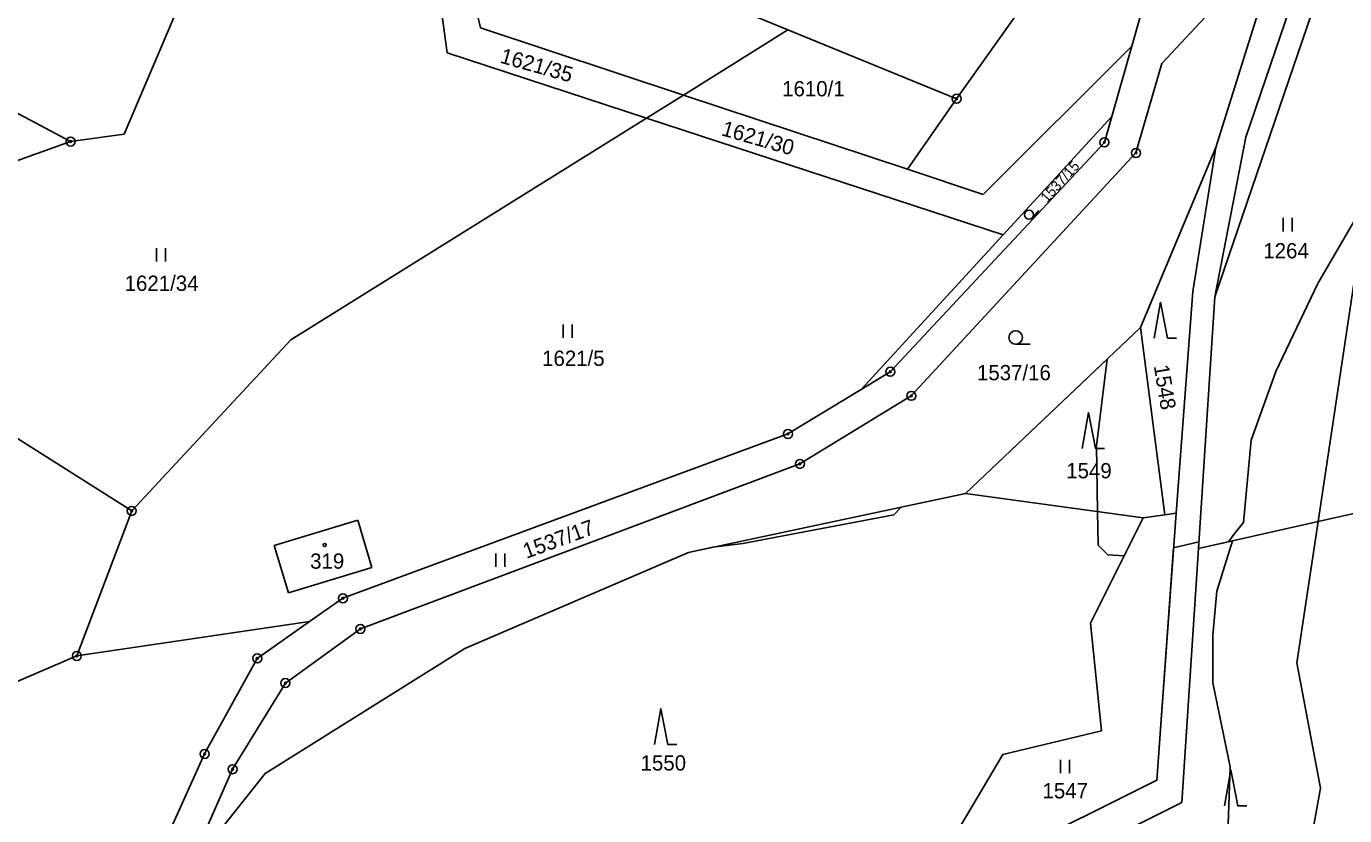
# Model space of a CAD drawing. Extents: x -445050 to -440454, y -1134563 to -1129741.
# Drawn here: x -442215.5 to -442068.8, y -1132304 to -1132216.1 of the extents above; entities that cross this region are included whole.
import ezdxf

# ---------------------------------------------------------------- set-up
doc = ezdxf.new("R2010")
doc.units = 0
for name, color, linetype in [('Vrstva 1', 7, 'Continuous'), ('Vrstva 18', 7, 'Continuous'), ('Vrstva 19', 7, 'Continuous'), ('Vrstva 24', 7, 'Continuous'), ('Vrstva 25', 7, 'Continuous'), ('Vrstva 3', 7, 'Continuous'), ('Vrstva 37', 7, 'Continuous'), ('Vrstva 52', 7, 'Continuous'), ('Vrstva 6', 7, 'Continuous')]:
    doc.layers.add(name, color=color, linetype=linetype)

msp = doc.modelspace()

# ---------------------------------------------------------------- linework, layer by layer
at = {"layer": 'Vrstva 1'}
for points in [[(-442079.79, -1132228.47), (-442069.94, -1132199.62)], [(-442168.65, -1132219.08), (-442171.25, -1132199.95)], [(-442168.53, -1132201.06), (-442130.72, -1132216.53)], [(-442168.53, -1132201.06), (-442164.95, -1132216.31)], [(-442087.74, -1132201.71), (-442092.48, -1132218.35)], [(-442250.43, -1132207.69), (-442210.55, -1132228.95)], [(-442080.57, -1132211.05), (-442089.13, -1132220.27)], [(-442083.13, -1132229.6), (-442077.5, -1132211.7)], [(-442198.19, -1132213.11), (-442204.59, -1132228.14)], [(-442104.18, -1132213.24), (-442111.96, -1132224.19)], [(-442083.23, -1132246.23), (-442072.42, -1132214.61)], [(-442164.95, -1132216.31), (-442142.36, -1132223.79)], [(-442142.36, -1132223.79), (-442130.72, -1132216.53)], [(-442130.72, -1132216.53), (-442111.96, -1132224.19)], [(-442108.99, -1132234.83), (-442092.48, -1132218.35)], [(-442092.48, -1132218.35), (-442094.7, -1132226.16)], [(-442168.65, -1132219.08), (-442146.45, -1132226.34)], [(-442089.13, -1132220.27), (-442092, -1132230.22)], [(-442146.45, -1132226.34), (-442142.36, -1132223.79)], [(-442142.36, -1132223.79), (-442117.44, -1132232.03)], [(-442111.96, -1132224.19), (-442117.44, -1132232.03)], [(-442186.05, -1132251.03), (-442146.45, -1132226.34)], [(-442146.45, -1132226.34), (-442106.78, -1132239.32)], [(-442094.7, -1132226.16), (-442106.78, -1132239.32)], [(-442094.7, -1132226.16), (-442095.52, -1132229.04)], [(-442210.55, -1132228.95), (-442232.96, -1132237.01)], [(-442204.59, -1132228.14), (-442210.55, -1132228.95)], [(-442083.23, -1132246.23), (-442079.79, -1132228.47)], [(-442119.34, -1132254.57), (-442095.52, -1132229.04)], [(-442092, -1132230.22), (-442117, -1132257.25)], [(-442091.48, -1132249.65), (-442083.13, -1132229.6)], [(-442085.69, -1132245.63), (-442083.13, -1132229.6)], [(-442071.73, -1132271.25), (-442065.52, -1132229.94)], [(-442117.44, -1132232.03), (-442108.99, -1132234.83)], [(-442106.78, -1132239.32), (-442122.59, -1132256.55)], [(-442087.54, -1132270.3), (-442085.69, -1132245.63)], [(-442083.23, -1132246.23), (-442085.05, -1132274.25)], [(-442186.05, -1132251.03), (-442203.74, -1132270.05)], [(-442091.48, -1132249.65), (-442110.98, -1132268.11)], [(-442091.48, -1132249.65), (-442088.78, -1132270.48)], [(-442119.34, -1132254.57), (-442122.59, -1132256.55)], [(-442122.59, -1132256.55), (-442130.72, -1132261.49)], [(-442117, -1132257.25), (-442129.4, -1132264.82)], [(-442217.56, -1132261.28), (-442203.74, -1132270.05)], [(-442180.25, -1132279.78), (-442130.72, -1132261.49)], [(-442129.4, -1132264.82), (-442178.3, -1132283.19)], [(-442110.98, -1132268.11), (-442141.8, -1132274.69)], [(-442110.98, -1132268.11), (-442091.21, -1132270.83)], [(-442203.74, -1132270.05), (-442209.85, -1132286.2)], [(-442178.6, -1132271.1), (-442187.88, -1132273.89)], [(-442177.02, -1132276.36), (-442178.6, -1132271.1)], [(-442091.21, -1132270.83), (-442097.06, -1132282.55)], [(-442091.21, -1132270.83), (-442088.78, -1132270.48)], [(-442089.68, -1132300.03), (-442087.54, -1132270.3)], [(-442088.78, -1132270.48), (-442087.54, -1132270.3)], [(-442085.05, -1132274.25), (-442071.73, -1132271.25)], [(-442074.09, -1132286.98), (-442071.73, -1132271.25)], [(-442187.88, -1132273.89), (-442186.3, -1132279.16)], [(-442085.05, -1132274.25), (-442086.89, -1132302.49)], [(-442141.8, -1132274.69), (-442166.69, -1132285.36)], [(-442186.3, -1132279.16), (-442177.02, -1132276.36)], [(-442183.96, -1132282.38), (-442180.25, -1132279.78)], [(-442209.85, -1132286.2), (-442183.96, -1132282.38)], [(-442189.78, -1132286.47), (-442183.96, -1132282.38)], [(-442178.3, -1132283.19), (-442186.65, -1132289.22)], [(-442097.06, -1132282.55), (-442095.83, -1132294.53)], [(-442209.85, -1132286.2), (-442254.86, -1132305.55)], [(-442166.69, -1132285.36), (-442188.9, -1132299.28)], [(-442195.63, -1132297.1), (-442189.78, -1132286.47)], [(-442071.47, -1132300.93), (-442074.09, -1132286.98)], [(-442186.65, -1132289.22), (-442192.52, -1132298.8)], [(-442095.83, -1132294.53), (-442106.83, -1132297.15)], [(-442211.4, -1132332.11), (-442195.63, -1132297.1)], [(-442106.83, -1132297.15), (-442115.37, -1132311.62)], [(-442197.5, -1132310.13), (-442192.52, -1132298.8)], [(-442188.9, -1132299.28), (-442197.5, -1132310.13)], [(-442089.68, -1132300.03), (-442106.41, -1132308.36)], [(-442074.56, -1132317.95), (-442071.47, -1132300.93)], [(-442103.13, -1132310.63), (-442086.89, -1132302.49)]]:
    msp.add_lwpolyline(points, dxfattribs=at)
at = {"layer": 'Vrstva 24'}
for centre, radius in [((-442111.96, -1132224.19), 0.5), ((-442111.96, -1132224.19), 0.1), ((-442210.55, -1132228.95), 0.5), ((-442210.55, -1132228.95), 0.1), ((-442095.52, -1132229.04), 0.5), ((-442095.52, -1132229.04), 0.1), ((-442092, -1132230.22), 0.5), ((-442092, -1132230.22), 0.1), ((-442119.34, -1132254.57), 0.5), ((-442119.34, -1132254.57), 0.1), ((-442117, -1132257.25), 0.5), ((-442117, -1132257.25), 0.1), ((-442130.72, -1132261.49), 0.5), ((-442130.72, -1132261.49), 0.1), ((-442129.4, -1132264.82), 0.5), ((-442129.4, -1132264.82), 0.1), ((-442203.74, -1132270.05), 0.5), ((-442203.74, -1132270.05), 0.1), ((-442180.25, -1132279.78), 0.5), ((-442180.25, -1132279.78), 0.1), ((-442178.3, -1132283.19), 0.5), ((-442178.3, -1132283.19), 0.1), ((-442209.85, -1132286.2), 0.5), ((-442209.85, -1132286.2), 0.1), ((-442189.78, -1132286.47), 0.5), ((-442189.78, -1132286.47), 0.1), ((-442186.65, -1132289.22), 0.5), ((-442186.65, -1132289.22), 0.1), ((-442195.63, -1132297.1), 0.5), ((-442195.63, -1132297.1), 0.1), ((-442192.52, -1132298.8), 0.5), ((-442192.52, -1132298.8), 0.1)]:
    msp.add_circle(centre, radius, dxfattribs=at)
at = {"layer": 'Vrstva 25'}
for p, q in [((-442103.52, -1132237.43), (-442102.82, -1132236.61)), ((-442075.62, -1132238.95), (-442075.62, -1132237.45)), ((-442074.62, -1132238.95), (-442074.62, -1132237.45)), ((-442201, -1132242.31), (-442201, -1132240.81)), ((-442200, -1132242.31), (-442200, -1132240.81)), ((-442155.74, -1132250.8), (-442155.74, -1132249.3)), ((-442154.74, -1132250.8), (-442154.74, -1132249.3)), ((-442105.39, -1132251.51), (-442103.79, -1132251.51)), ((-442163.24, -1132276.29), (-442163.24, -1132274.79)), ((-442162.24, -1132276.29), (-442162.24, -1132274.79)), ((-442100.41, -1132299.26), (-442100.41, -1132297.76)), ((-442099.41, -1132299.26), (-442099.41, -1132297.76))]:
    msp.add_line(p, q, dxfattribs=at)
for points in [[(-442089.98, -1132250.83), (-442089.28, -1132246.83), (-442088.48, -1132250.83), (-442087.48, -1132250.83)], [(-442098, -1132263.12), (-442097.3, -1132259.12), (-442096.5, -1132263.12), (-442095.5, -1132263.12)], [(-442145.58, -1132296.07), (-442144.88, -1132292.07), (-442144.08, -1132296.07), (-442143.08, -1132296.07)], [(-442082.16, -1132302.89), (-442081.46, -1132298.89), (-442080.66, -1132302.89), (-442079.66, -1132302.89)]]:
    msp.add_lwpolyline(points, dxfattribs=at)
for centre, radius in [((-442103.9, -1132237.1), 0.503), ((-442105.39, -1132250.76), 0.75), ((-442182.27, -1132273.85), 0.175)]:
    msp.add_circle(centre, radius, dxfattribs=at)
at = {"layer": 'Vrstva 3'}
for points in [[(-442178.6, -1132271.1), (-442187.88, -1132273.89)], [(-442177.02, -1132276.36), (-442178.6, -1132271.1)], [(-442187.88, -1132273.89), (-442186.3, -1132279.16)], [(-442186.3, -1132279.16), (-442177.02, -1132276.36)]]:
    msp.add_lwpolyline(points, dxfattribs=at)
at = {"layer": 'Vrstva 37'}
msp.add_circle((-442182.27, -1132273.85), 0.175, dxfattribs=at)
at = {"layer": 'Vrstva 52'}
for points in [[(-442081.7, -1132273.49), (-442080.99, -1132272.52), (-442080.05, -1132271.33), (-442079.2, -1132262.19), (-442076.43, -1132254.54), (-442071.76, -1132244.76), (-442066.35, -1132235.45), (-442062.62, -1132229.03), (-442048.59, -1132210.97), (-442040.34, -1132204.15), (-442037.54, -1132201.83), (-442029.89, -1132197.15), (-442024.79, -1132194.6), (-442020.54, -1132193.33), (-442004.38, -1132185.04), (-442003.24, -1132184.71), (-441998.43, -1132183.34), (-441989.7, -1132178.08)], [(-442197.5, -1132310.13), (-442188.9, -1132299.28), (-442166.69, -1132285.36), (-442141.8, -1132274.69), (-442139.09, -1132274.11), (-442135.73, -1132273.67), (-442118.94, -1132270.48), (-442118.14, -1132269.64), (-442110.98, -1132268.11), (-442095.21, -1132253.18), (-442096.41, -1132262.83), (-442096.27, -1132270.13), (-442096.2, -1132273.88), (-442095.14, -1132274.94), (-442093.32, -1132275.06), (-442097.06, -1132282.55), (-442095.83, -1132294.53), (-442106.83, -1132297.15), (-442115.37, -1132311.62)], [(-442081.7, -1132273.49), (-442081.27, -1132273.4), (-442083.02, -1132278.98), (-442083.45, -1132283.87), (-442083.45, -1132289.18), (-442081.53, -1132298.53), (-442081.96, -1132311.29), (-442083.87, -1132318.09), (-442088.15, -1132321.69), (-442091.95, -1132324.89), (-442090.04, -1132328.71), (-442088.93, -1132329.88), (-442081.36, -1132337.86), (-442072.75, -1132335.74), (-442072.69, -1132335.79), (-442065.44, -1132333.93), (-442050.29, -1132330.2), (-442049.58, -1132329.88), (-442047.64, -1132329.38), (-442045.19, -1132331.26), (-442043.91, -1132334.03), (-442044.62, -1132335.43), (-442044.76, -1132335.73), (-442112.61, -1132368.06)], [(-442106.41, -1132308.36), (-442089.68, -1132300.03), (-442087.82, -1132274.16), (-442085, -1132273.48), (-442085.05, -1132274.25), (-442081.7, -1132273.49)]]:
    msp.add_lwpolyline(points, dxfattribs=at)
at = {"layer": 'Vrstva 6'}
msp.add_lwpolyline([(-441952.83, -1132244.54), (-442071.73, -1132271.25)], dxfattribs=at)

# ---------------------------------------------------------------- texts
at = {"layer": 'Vrstva 18'}
for s, height, rotation, p in [('1621/35', 1.7, 344.3337, (-442162.86, -1132220.16)), ('1621/30', 1.7, 343.8828, (-442138.23, -1132228.23)), ('1537/15', 1.14, 47.8466, (-442101.89, -1132235.83)), ('1548', 1.7, 279.4122, (-442090.03, -1132253.92)), ('1537/17', 1.7, 20.1735, (-442159.83, -1132275.4))]:
    msp.add_text(s, height=height, rotation=rotation, dxfattribs=at).set_placement(p)
for s, p in [('1610/1', (-442131.37, -1132223.92)), ('1264', (-442077.83, -1132241.95)), ('1621/34', (-442204.53, -1132245.57)), ('1621/5', (-442158.08, -1132253.92)), ('1537/16', (-442109.69, -1132255.52)), ('1549', (-442099.76, -1132266.43)), ('1550', (-442147.12, -1132298.95)), ('1547', (-442102.4, -1132302.05))]:
    msp.add_text(s, height=1.7, dxfattribs=at).set_placement(p)
at = {"layer": 'Vrstva 19'}
msp.add_text('319', height=1.7, dxfattribs=at).set_placement((-442183.89, -1132276.49))

doc.saveas('drawing.dxf')
